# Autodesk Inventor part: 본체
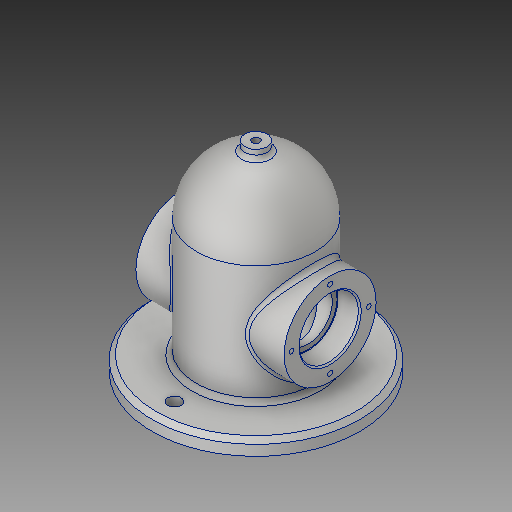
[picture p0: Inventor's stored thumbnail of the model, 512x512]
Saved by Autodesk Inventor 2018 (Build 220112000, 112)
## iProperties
Created: 2019-11
Part Number: 본체
Material: 알루미늄 6061
Document SubType Name: Modeling
Designer: Administrator
Density: 2.7 g/cm^3
Appearance: 알루미늄 - 평지
Mass: 1103.13 g
Surface Area: 881.129 cm^2
Volume: 408.566 cm^3
Author: Administrator
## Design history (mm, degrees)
sketch "스케치1"
  geometry: C1 r 70 at (0, 0); 1 further point
  constraints: 1 centre point, 1 coincident
  dimensions: "d0" = 140 diameter of C1
extrude "돌출1" new body sketch "스케치1" distance "d1" = 10; taper "d2" = 0 deg
sketch "스케치2"
  geometry: C1 r 40 at (0, 0); 1 further point
  constraints: 1 centre point, 1 coincident
  dimensions: "d3" = 80 diameter of C1
extrude "돌출2" join sketch "스케치2" distance "d4" = 80; taper "d5" = 0 deg
sketch "스케치4"
  geometry: L1 (90, -40)-(90, 40) reference; L2 (90, 0)-(130, 0); L3 (90, 40)-(90, 0); A1 r 40 centre (90, 0) between (130, 0) and (90, 40); 1 further point
  constraints: 5 end point, 2 point on circle, 1 centre point, 1 coincident, 1 collinear, 1 horizontal, 1 midpoint, 1 point on line
revolve "회전1" sketch "스케치4" stored, may be unused: angle "d7" = 90 deg
chamfer "모따기1" distance "d8" = 3; stored, may be unused: second distance "d9" = 2, angle "d10" = 45 deg
sketch "스케치5"
  geometry: C1 r 31 at (50, 0); 1 further point
  constraints: 1 centre point
extrude "돌출3" join sketch "스케치5" stored distance "d13" = 100; taper "d14" = 0 deg
sketch "스케치6"
  geometry: C1 r 20 at (0, 0); 1 further point
  constraints: 1 centre point
  dimensions: "d15" = 40 diameter of C1
extrude "돌출4" cut sketch "스케치6" distance "d16" = 15; taper "d17" = 0 deg
sketch "스케치7"
  geometry: C1 r 16.5 at (0, 0); 1 further point
  constraints: 1 centre point
  dimensions: "d18" = 33 diameter of C1
extrude "돌출5" cut sketch "스케치7" extent not by distance; stored distance "d19" = 15; taper "d20" = 0 deg
chamfer "모따기2" distance "d21" = 1; stored, may be unused: second distance "d22" = 2, angle "d23" = 45 deg
fillet "모깎기1" dims "d24" = 0.3
sketch "스케치8"
  geometry: 5 further points
hole "구멍1" sketch "스케치8" at (0, 26), (-26, 0), (0, -26), (26, 0) diameter "d26" = 3.242; stored, may be unused: countersink angle "d30" = 90 deg, drill point angle "d32" = 118 deg; dims "d27" = 8, "d28" = 4, "d29" = 2, "d31" = 10
sketch "스케치9"
  geometry: C1 r 30 at (0, 0); 1 further point
  constraints: 1 centre point, 1 coincident
  dimensions: "d33" = 60 diameter of C1
extrude "돌출6" cut sketch "스케치9" distance "d34" = 90; taper "d35" = 0 deg
sketch "스케치11"
  geometry: L1 (90, -40)-(90, 40) reference; L2 (90, 0)-(120, 0); L3 (90, 0)-(90, 30); A1 r 30 centre (90, 0) between (120, 0) and (90, 30); 1 further point
  constraints: 4 end point, 2 point on circle, 1 centre point, 1 collinear, 1 midpoint, 1 point on line
revolve "회전2" sketch "스케치11" stored, may be unused: angle "d39" = 90 deg
sketch "스케치12"
  geometry: C1 r 4.5 at (0, -55); C2 r 4.5 at (0, 55); 1 further point
  constraints: 2 centre point
  dimensions: "d41" = 9 diameter of C1; "d42" = 9 diameter of C2
extrude "돌출7" cut sketch "스케치12" extent not by distance; stored distance "d43" = 90; taper "d44" = 0 deg
node "작업 평면2"
  node "작업 평면1"
sketch "스케치13"
  geometry: C1 r 7.5 at (0, 0); 1 further point
  constraints: 1 centre point, 1 coincident
  dimensions: "d46" = 15 diameter of C1
extrude "돌출8" join sketch "스케치13" distance "d47" = 7; taper "d48" = 0 deg
sketch "스케치14"
  geometry: 2 further points
  constraints: 1 coincident
hole "구멍2" sketch "스케치14" at (0, 0) diameter "d49" = 5.188; stored, may be unused: countersink angle "d53" = 90 deg, drill point angle "d55" = 118 deg; dims "d50" = 12, "d51" = 4, "d52" = 2, "d54" = 16
fillet "모깎기2" dims "d56" = 3
fillet "모깎기3" dims "d57" = 3
node "작업 평면3"
sketch "스케치15"
  geometry: L1 (-70, -10)-(70, -10) reference; 3 further points
  constraints: 1 midpoint, 1 vertical alignment, 1 other
feature "엠보싱1" sketch "스케치15" dims "d59" = 0.5, "d60" = 0
node "솔리드1"
mirror "미러1"
mirror "미러2"
other parameters: "d45" = -2
